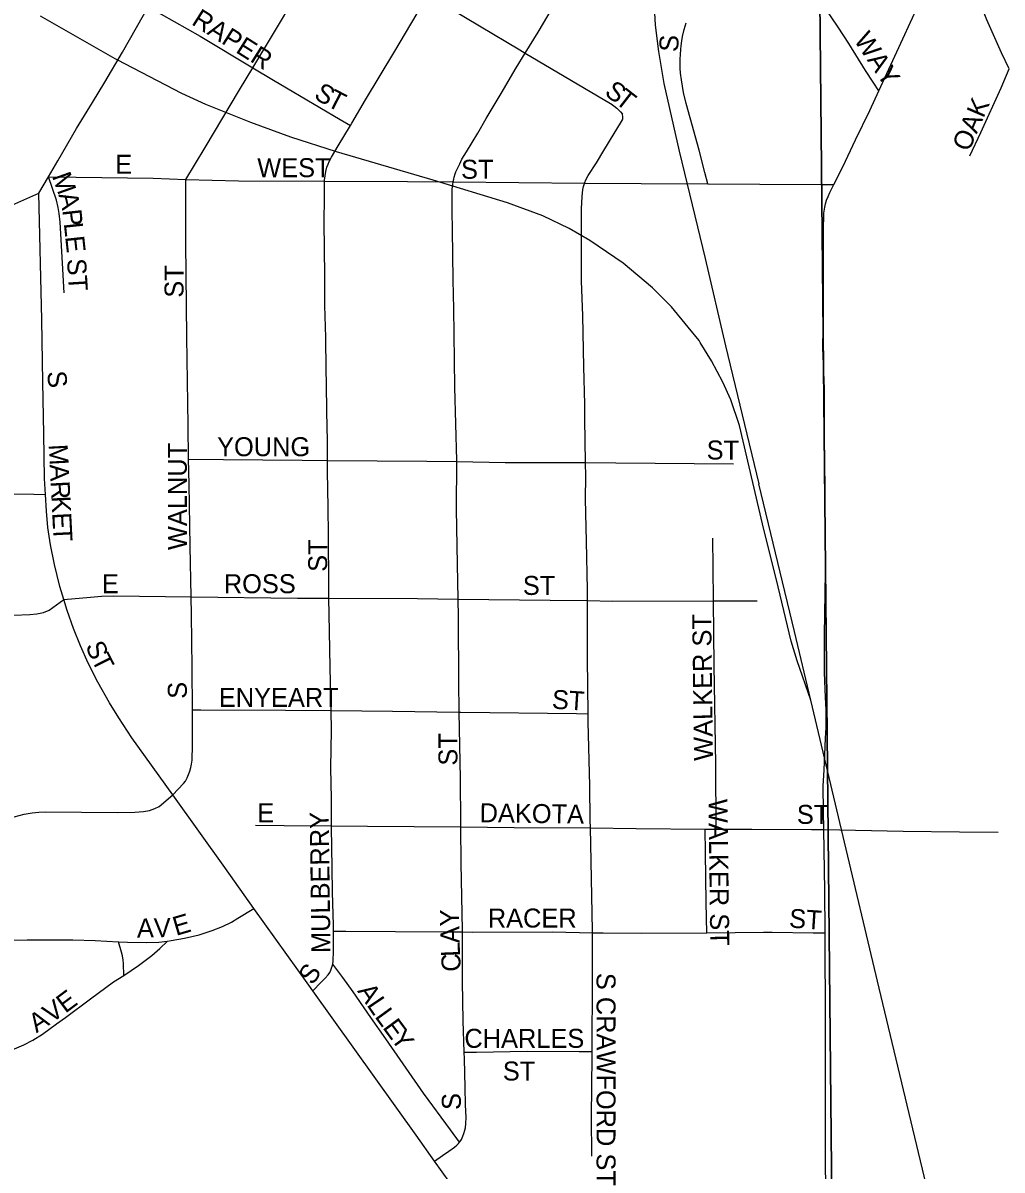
# Model space of a CAD drawing. Extents: x 0 to 680, y 0 to 440.
# Drawn here: x 482.76 to 491.37, y 313.37 to 323.45 of the extents above; entities that cross this region are included whole.
import ezdxf

# ---------------------------------------------------------------- set-up
doc = ezdxf.new("R2010")
doc.units = 0
for name, color, linetype in [('GM_X_City_Street', 7, 'Continuous'), ('GM_X_City_Street_Text', 7, 'Continuous'), ('GM_X_Rail_Line', 7, 'Continuous'), ('GM_X_Section', 7, 'Continuous'), ('GM_X_State_Route', 7, 'Continuous')]:
    doc.layers.add(name, color=color, linetype=linetype)

msp = doc.modelspace()

# ---------------------------------------------------------------- linework, layer by layer
at = {"layer": 'GM_X_City_Street'}
for points in [[(490.287, 322.848), (490.237, 322.925), (490.171, 323.028), (490.024, 323.264), (489.931, 323.409), (489.735, 323.702), (489.484, 324.108), (489.393, 324.249), (489.228, 324.508), (489.189, 324.563)], [(487.179, 323.18), (487.292, 323.364), (487.567, 323.832), (487.764, 324.162), (487.814, 324.249), (487.821, 324.267), (487.824, 324.287), (487.826, 324.309), (487.826, 324.375)], [(484.783, 323.051), (484.982, 323.382), (485.467, 324.192)], [(490.287, 322.848), (490.498, 323.306), (490.633, 323.599), (490.905, 324.183)], [(491.433, 323.041), (491.366, 323.184), (491.238, 323.474), (491.196, 323.575), (491.065, 323.909), (491.048, 323.942), (491.027, 323.986), (491.004, 324.024), (490.983, 324.06), (490.966, 324.088), (490.935, 324.135), (490.905, 324.183)], [(485.643, 322.545), (485.655, 322.564), (485.776, 322.769), (486.033, 323.198), (486.324, 323.688)], [(486.324, 323.688), (486.421, 323.631), (487.131, 323.208), (487.179, 323.18)], [(483.864, 323.586), (484.321, 323.328), (484.783, 323.051)], [(488.783, 322.031), (488.758, 322.13), (488.708, 322.327), (488.63, 322.611), (488.595, 322.736), (488.571, 322.834), (488.553, 322.946), (488.543, 323.005), (488.542, 323.048), (488.54, 323.089), (488.542, 323.13), (488.543, 323.165), (488.548, 323.214), (488.55, 323.243), (488.556, 323.289), (488.561, 323.325), (488.576, 323.388), (488.594, 323.447)], [(486.545, 322.048), (486.546, 322.052), (486.55, 322.072), (486.555, 322.09), (486.562, 322.118), (486.57, 322.136), (486.578, 322.155), (486.588, 322.179), (486.603, 322.208), (486.623, 322.247), (486.662, 322.313), (486.761, 322.476), (486.836, 322.605), (486.968, 322.825), (487.1, 323.052), (487.179, 323.18)], [(487.179, 323.18), (487.929, 322.737), (487.934, 322.734), (487.959, 322.716), (487.983, 322.697), (488.018, 322.664), (488.035, 322.644)], [(484.196, 322.07), (484.366, 322.35), (484.666, 322.858), (484.783, 323.051)], [(484.783, 323.051), (484.967, 322.943), (485.374, 322.703), (485.553, 322.598), (485.643, 322.545)], [(491.089, 322.278), (491.184, 322.482), (491.362, 322.875), (491.433, 323.041)], [(489.893, 322.026), (489.972, 322.18), (490.084, 322.418), (490.208, 322.675), (490.287, 322.848)], [(487.701, 322.038), (487.716, 322.072), (487.733, 322.105), (487.805, 322.216), (487.871, 322.323), (487.961, 322.473), (488.017, 322.564), (488.026, 322.579), (488.034, 322.595), (488.036, 322.603), (488.037, 322.619), (488.035, 322.644)], [(485.415, 322.055), (485.415, 322.064), (485.419, 322.103), (485.426, 322.141), (485.436, 322.177), (485.447, 322.203), (485.456, 322.227), (485.476, 322.266), (485.534, 322.366), (485.643, 322.545)], [(483.125, 321.074), (483.111, 321.333), (483.091, 321.694), (483.082, 321.77), (483.074, 321.823), (483.057, 321.887), (482.989, 322.094)], [(482.989, 322.094), (483.23, 322.091), (483.907, 322.082), (484.196, 322.07)], [(484.219, 319.613), (484.215, 319.912), (484.204, 320.683), (484.194, 321.514), (484.196, 322.07)], [(484.196, 322.07), (484.657, 322.059), (485.415, 322.055)], [(485.441, 319.601), (485.44, 319.774), (485.436, 320.029), (485.431, 320.277), (485.428, 320.397), (485.425, 320.68), (485.418, 320.962), (485.418, 321.213), (485.414, 321.468), (485.411, 321.683), (485.415, 321.924), (485.415, 322.055)], [(485.415, 322.055), (486.145, 322.051), (486.545, 322.048)], [(486.578, 319.59), (486.579, 319.599), (486.561, 320.244), (486.554, 320.714), (486.55, 320.93), (486.546, 321.189), (486.539, 321.626), (486.538, 321.79), (486.538, 321.942), (486.538, 321.985), (486.542, 322.025), (486.545, 322.048)], [(486.545, 322.048), (487.701, 322.038)], [(487.709, 319.582), (487.702, 319.964), (487.703, 320.094), (487.694, 320.423), (487.685, 320.871), (487.675, 321.178), (487.675, 321.243), (487.675, 321.813), (487.68, 321.92), (487.685, 321.981), (487.692, 322.007), (487.699, 322.034), (487.701, 322.038)], [(487.701, 322.038), (488.199, 322.034), (488.783, 322.031)], [(488.783, 322.031), (489.243, 322.029), (489.777, 322.027), (489.893, 322.026)], [(489.81, 317.893), (489.81, 318.064), (489.819, 318.62), (489.816, 319.351), (489.811, 319.805), (489.809, 320.229), (489.796, 320.593), (489.802, 320.921), (489.801, 321.294), (489.802, 321.666), (489.804, 321.724), (489.805, 321.774), (489.812, 321.827), (489.82, 321.857), (489.828, 321.887), (489.842, 321.92), (489.858, 321.956), (489.893, 322.026)], [(482.938, 320.29), (482.929, 320.836), (482.904, 321.948)], [(482.961, 319.302), (482.954, 319.441), (482.946, 319.835), (482.938, 320.29)], [(484.243, 318.401), (484.233, 318.848), (484.223, 319.391), (484.219, 319.613)], [(484.219, 319.613), (484.527, 319.61), (485.219, 319.603), (485.441, 319.601)], [(485.453, 318.39), (485.452, 318.505), (485.448, 318.944), (485.447, 319.189), (485.441, 319.503), (485.441, 319.601)], [(485.441, 319.601), (486.314, 319.594), (486.578, 319.59)], [(486.589, 318.383), (486.584, 318.69), (486.574, 319.172), (486.578, 319.59)], [(486.578, 319.59), (487.004, 319.584), (487.709, 319.582)], [(487.727, 318.369), (487.727, 318.463), (487.718, 318.89), (487.715, 319.012), (487.71, 319.263), (487.711, 319.46), (487.709, 319.582)], [(487.709, 319.582), (487.977, 319.581), (489.009, 319.571)], [(481.026, 319.289), (481.055, 319.303), (481.084, 319.307), (481.122, 319.308), (481.165, 319.307), (481.195, 319.307), (481.742, 319.311), (482.518, 319.306), (482.86, 319.303), (482.961, 319.302)], [(483.123, 318.378), (483.088, 318.492), (483.041, 318.685), (483.005, 318.858), (482.983, 319.012), (482.969, 319.155), (482.961, 319.302)], [(488.835, 318.366), (488.83, 318.66), (488.827, 318.918)], [(481.021, 318.241), (481.773, 318.235), (482.417, 318.238), (482.68, 318.241), (482.823, 318.247), (482.885, 318.253), (482.945, 318.266), (482.994, 318.284), (483.123, 318.378)], [(483.123, 318.378), (483.358, 318.399), (483.454, 318.407), (483.563, 318.411), (484.243, 318.401)], [(484.08, 316.663), (483.721, 317.164), (483.605, 317.338), (483.524, 317.47), (483.422, 317.653), (483.337, 317.82), (483.268, 317.971), (483.207, 318.125), (483.152, 318.281), (483.123, 318.378)], [(484.243, 318.401), (485.177, 318.391), (485.453, 318.39)], [(484.255, 317.408), (484.252, 317.777), (484.245, 318.247), (484.243, 318.401)], [(485.453, 318.39), (486.232, 318.387), (486.589, 318.383)], [(485.473, 317.403), (485.473, 317.404), (485.463, 317.781), (485.457, 318.101), (485.453, 318.39)], [(486.589, 318.383), (487.399, 318.374), (487.727, 318.369)], [(486.599, 317.388), (486.599, 317.41), (486.595, 317.638), (486.592, 318.226), (486.589, 318.383)], [(487.732, 317.375), (487.725, 317.859), (487.727, 318.369)], [(487.727, 318.369), (487.947, 318.365), (488.835, 318.366)], [(488.835, 318.366), (489.028, 318.366), (489.218, 318.367)], [(488.859, 316.361), (488.856, 316.933), (488.841, 317.799), (488.835, 318.366)], [(489.804, 316.358), (489.802, 316.519), (489.799, 316.739), (489.807, 316.881), (489.813, 317.015), (489.82, 317.161), (489.824, 317.253), (489.825, 317.337), (489.826, 317.408), (489.823, 317.464), (489.82, 317.518), (489.811, 317.736), (489.81, 317.893)], [(484.08, 316.663), (484.174, 316.761), (484.192, 316.783), (484.208, 316.811), (484.22, 316.84), (484.23, 316.869), (484.24, 316.902), (484.245, 316.933), (484.25, 316.967), (484.252, 317.01), (484.254, 317.054), (484.255, 317.408)], [(484.255, 317.408), (484.328, 317.408), (485.072, 317.407), (485.473, 317.403)], [(485.477, 316.389), (485.476, 316.628), (485.471, 316.901), (485.475, 317.23), (485.473, 317.403)], [(485.473, 317.403), (486.012, 317.398), (486.599, 317.388)], [(486.614, 316.38), (486.614, 316.413), (486.611, 316.805), (486.599, 317.388)], [(486.599, 317.388), (486.614, 317.388), (487.631, 317.377), (487.732, 317.375)], [(487.752, 316.371), (487.75, 316.441), (487.747, 316.742), (487.733, 317.303), (487.732, 317.375)], [(482.489, 316.4), (482.687, 316.469), (482.773, 316.492), (482.844, 316.505), (482.902, 316.51), (482.958, 316.513), (483.596, 316.508), (483.748, 316.51), (483.823, 316.516), (483.875, 316.526), (483.924, 316.542), (483.961, 316.56), (484.08, 316.663)], [(484.794, 315.664), (484.794, 315.664), (484.537, 316.023), (484.08, 316.663)], [(484.809, 316.395), (485.06, 316.393), (485.477, 316.389)], [(485.477, 316.389), (485.792, 316.386), (486.614, 316.38)], [(485.493, 315.463), (485.492, 315.517), (485.484, 315.808), (485.482, 316.022), (485.477, 316.377), (485.477, 316.389)], [(486.628, 315.457), (486.628, 315.475), (486.617, 316.059), (486.614, 316.38)], [(486.614, 316.38), (487.083, 316.376), (487.752, 316.371)], [(487.769, 315.45), (487.769, 315.471), (487.756, 316.228), (487.752, 316.371)], [(487.752, 316.371), (488.155, 316.367), (488.76, 316.361)], [(488.76, 316.361), (488.859, 316.361)], [(488.775, 315.451), (488.771, 315.716), (488.763, 316.156), (488.76, 316.361)], [(488.859, 316.361), (489.172, 316.361), (489.697, 316.359), (489.804, 316.358)], [(489.804, 316.358), (490.503, 316.342), (490.998, 316.337), (491.337, 316.334)], [(489.816, 315.449), (489.816, 315.456), (489.814, 315.821), (489.804, 316.358)], [(484.034, 315.377), (484.066, 315.381), (484.184, 315.402), (484.312, 315.433), (484.427, 315.469), (484.518, 315.505), (484.597, 315.544), (484.653, 315.578), (484.794, 315.664)], [(485.311, 314.94), (485.311, 314.94), (485.276, 314.99), (484.794, 315.664)], [(485.487, 315.175), (485.491, 315.202), (485.494, 315.288), (485.493, 315.357), (485.493, 315.463)], [(485.493, 315.463), (485.602, 315.463), (486.476, 315.458), (486.628, 315.457)], [(486.642, 314.401), (486.634, 314.675), (486.627, 315.023), (486.628, 315.457)], [(486.628, 315.457), (486.713, 315.456), (487.415, 315.457), (487.656, 315.452), (487.769, 315.45)], [(487.768, 314.407), (487.769, 315.046), (487.769, 315.45)], [(487.769, 315.45), (487.864, 315.449), (488.203, 315.446), (488.775, 315.451)], [(488.775, 315.451), (489.275, 315.455), (489.351, 315.455), (489.71, 315.451), (489.816, 315.449)], [(489.822, 313.166), (489.818, 313.477), (489.818, 313.794), (489.818, 314.309), (489.819, 314.638), (489.816, 315.449)], [(481.071, 315.378), (481.322, 315.376), (481.585, 315.379), (481.891, 315.381), (482.8, 315.388), (483.203, 315.387), (483.399, 315.381), (483.602, 315.372)], [(483.602, 315.372), (483.683, 315.368), (483.847, 315.365), (483.957, 315.369), (484.034, 315.377)], [(483.65, 315.076), (483.646, 315.179), (483.643, 315.21), (483.637, 315.248), (483.63, 315.281), (483.602, 315.372)], [(483.65, 315.076), (483.779, 315.164), (483.895, 315.25), (483.966, 315.312), (484.034, 315.377)], [(485.311, 314.94), (485.383, 315.014), (485.42, 315.052), (485.447, 315.081), (485.461, 315.101), (485.471, 315.122), (485.48, 315.147), (485.487, 315.174), (485.487, 315.175)], [(486.601, 313.609), (486.521, 313.719), (486.284, 314.041), (485.952, 314.519), (485.822, 314.707), (485.665, 314.93), (485.574, 315.056), (485.487, 315.175)], [(481.08, 314.358), (481.102, 314.353), (481.161, 314.345), (481.26, 314.338), (481.545, 314.336), (481.895, 314.342), (482.169, 314.349), (482.281, 314.354), (482.372, 314.36), (482.475, 314.377), (482.593, 314.402), (482.688, 314.431), (482.77, 314.464), (482.85, 314.505), (482.934, 314.559), (483.058, 314.65), (483.138, 314.707), (483.357, 314.869), (483.56, 315.018), (483.65, 315.076)], [(486.381, 313.443), (486.381, 313.443), (486.219, 313.671), (485.311, 314.94)], [(486.642, 314.401), (486.751, 314.402), (487.197, 314.409), (487.654, 314.407), (487.768, 314.407)], [(487.766, 313.488), (487.761, 313.833), (487.768, 314.366), (487.768, 314.407)], [(486.601, 313.609), (486.604, 313.613), (486.618, 313.634), (486.63, 313.662), (486.64, 313.687), (486.649, 313.716), (486.655, 313.737), (486.657, 313.774), (486.66, 313.827), (486.654, 313.938), (486.651, 314.091), (486.644, 314.343), (486.642, 314.401)], [(486.381, 313.443), (486.452, 313.492), (486.506, 313.53), (486.558, 313.565), (486.577, 313.583), (486.593, 313.597), (486.601, 313.609)], [(486.583, 313.161), (486.381, 313.443)]]:
    msp.add_lwpolyline(points, dxfattribs=at)
at = {"layer": 'GM_X_Rail_Line'}
for points in [[(492.717, 332.516), (490.623, 328.994), (489.818, 327.634), (488.984, 326.25), (488.832, 325.981), (488.751, 325.816), (488.679, 325.663), (488.619, 325.509), (488.55, 325.316), (488.504, 325.171), (488.461, 325.005), (488.422, 324.838), (488.379, 324.626), (488.346, 324.449), (488.323, 324.222), (488.309, 323.969), (488.308, 323.694), (488.321, 323.425), (488.351, 323.194), (488.397, 322.914), (488.532, 322.319), (488.76, 321.376), (488.94, 320.609)], [(483.573, 323.131), (482.916, 323.504)], [(483.592, 323.121), (483.573, 323.131)], [(488.708, 320.656), (488.611, 320.773), (488.464, 320.95), (488.299, 321.117), (488.039, 321.333), (487.747, 321.534), (487.566, 321.639), (487.334, 321.751), (487.024, 321.864), (486.371, 322.064), (485.521, 322.314), (485.119, 322.441), (484.768, 322.569), (484.37, 322.728), (484.159, 322.824), (483.592, 323.121)], [(488.718, 320.638), (488.708, 320.656)], [(489.691, 317.493), (489.569, 317.841), (489.516, 318.014), (489.404, 318.489), (489.266, 319.043), (489.064, 319.907), (488.988, 320.132), (488.915, 320.29), (488.816, 320.476), (488.718, 320.638)], [(488.94, 320.609), (489.234, 319.395)], [(489.691, 317.493), (489.547, 318.099), (489.234, 319.395)], [(491.1, 311.586), (490.29, 314.963), (489.959, 316.358), (489.691, 317.493)]]:
    msp.add_lwpolyline(points, dxfattribs=at)
at = {"layer": 'GM_X_Section'}
msp.add_lwpolyline([(489.695, 330.98), (489.874, 313.088), (471.837, 312.991), (471.834, 331.06)], close=True, dxfattribs=at)
msp.add_lwpolyline([(489.874, 313.088), (489.695, 330.98), (491.217, 330.951), (492.745, 330.582)], dxfattribs=at)
at = {"layer": 'GM_X_State_Route'}
for points in [[(482.904, 321.948), (482.989, 322.094), (483.071, 322.235), (483.235, 322.517), (483.374, 322.745), (483.483, 322.924), (483.638, 323.189), (483.822, 323.513), (483.864, 323.586), (483.969, 323.768), (484.147, 324.057), (484.425, 324.53), (484.541, 324.738), (484.751, 325.087), (485.147, 325.741), (485.246, 325.91), (485.764, 326.787), (485.904, 327.024), (486.026, 327.228), (486.238, 327.584)], [(482.64, 321.833), (482.904, 321.948)]]:
    msp.add_lwpolyline(points, dxfattribs=at)

# ---------------------------------------------------------------- texts
at = {"layer": 'GM_X_City_Street_Text'}
for s, height, rotation, p in [('RAPER', 0.1669, 327.7209, (484.237, 323.437)), ('WAY', 0.1669, 303.6919, (490.063, 323.296)), ('S', 0.167, 86.6929, (488.522, 323.187)), ('S', 0.167, 328.2726, (485.312, 322.789)), ('S', 0.167, 322.9444, (487.867, 322.819)), ('T', 0.167, 322.01, (487.96, 322.748)), ('T', 0.167, 332.7794, (485.424, 322.721)), ('OAK', 0.1669, 66.8061, (491.08, 322.306)), ('E', 0.167, 0, (483.574, 322.12)), ('WEST', 0.1669, 0, (484.823, 322.09)), ('ST', 0.1669, 0, (486.615, 322.076)), ('M', 0.167, 289.5007, (483.017, 322.099)), ('A', 0.167, 283.9726, (483.074, 321.937)), ('P', 0.167, 276.4609, (483.109, 321.8)), ('L', 0.167, 276.1048, (483.122, 321.684)), ('E', 0.167, 276.1211, (483.134, 321.567)), ('ST', 0.1669, 273.5738, (483.15, 321.371)), ('ST', 0.1669, 90, (484.175, 321.031)), ('S', 0.167, 275.7077, (482.975, 320.38)), ('WALNUT', 0.1669, 90, (484.204, 318.813)), ('YOUNG', 0.1669, 0, (484.47, 319.638)), ('ST', 0.1669, 0, (488.774, 319.609)), ('M', 0.167, 272.9697, (482.989, 319.74)), ('A', 0.167, 272.9813, (482.998, 319.564)), ('R', 0.167, 272.9643, (483.006, 319.417)), ('K', 0.167, 272.9813, (483.013, 319.285)), ('E', 0.167, 272.9525, (483.02, 319.139)), ('T', 0.167, 272.9667, (483.026, 319.021)), ('ST', 0.1669, 90, (485.438, 318.622)), ('E', 0.167, 0, (483.457, 318.434)), ('ROSS', 0.1669, 0, (484.529, 318.434)), ('ST', 0.1669, 0, (487.158, 318.419)), ('WALKER ST', 0.1669, 90.7276, (488.83, 316.962)), ('S', 0.167, 292.8111, (483.31, 317.972)), ('T', 0.167, 297.0549, (483.361, 317.852)), ('S', 0.167, 90, (484.204, 317.506)), ('ENYEART', 0.1669, 0, (484.485, 317.435)), ('ST', 0.1669, 356.4126, (487.41, 317.42)), ('ST', 0.1669, 90, (486.583, 316.919)), ('WALKER ST', 0.1669, 270.7352, (488.79, 316.625)), ('E', 0.167, 0, (484.823, 316.421)), ('DAKOTA', 0.1669, 359.1692, (486.777, 316.422)), ('ST', 0.1669, 0, (489.567, 316.407)), ('MULBERRY', 0.1669, 90.7363, (485.467, 315.273)), ('E', 0.167, 16.3658, (484.109, 315.422)), ('Y', 0.167, 90.2405, (486.598, 315.506)), ('RACER', 0.1669, 0, (486.85, 315.496)), ('ST', 0.1669, 356.1879, (489.495, 315.496)), ('A', 0.167, 0.4591, (483.766, 315.408)), ('V', 0.167, 1.9089, (483.917, 315.409)), ('A', 0.167, 91.6834, (486.603, 315.36)), ('L', 0.167, 92.2404, (486.607, 315.243)), ('C', 0.167, 92.2596, (486.613, 315.111)), ('S', 0.167, 56.3015, (485.311, 314.983)), ('S CRAWFORD ST', 0.16689, 270, (487.806, 315.098)), ('E', 0.167, 36.8233, (483.136, 314.738)), ('A', 0.167, 303.9568, (485.699, 314.938)), ('V', 0.167, 35.4867, (483.013, 314.651)), ('L', 0.167, 304.0115, (485.781, 314.816)), ('A', 0.167, 32.7746, (482.882, 314.566)), ('L', 0.167, 306.0592, (485.851, 314.713)), ('E', 0.167, 306.4028, (485.92, 314.617)), ('Y', 0.167, 306.4504, (485.99, 314.522)), ('CHARLES', 0.1669, 0, (486.644, 314.439)), ('ST', 0.1669, 0, (486.982, 314.152)), ('S', 0.167, 90, (486.613, 313.893))]:
    msp.add_text(s, height=height, rotation=rotation, dxfattribs=at).set_placement(p)

doc.saveas('drawing.dxf')
